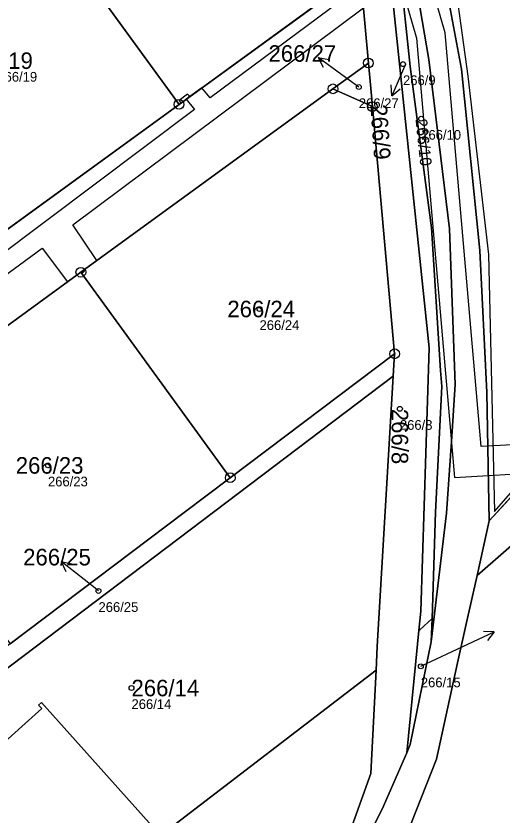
# Model space of a CAD drawing. Extents: x -734504 to -730695, y -1027923 to -1024502.
# Drawn here: x -732118.1 to -732068.2, y -1026667.3 to -1026585.2 of the extents above; entities that cross this region are included whole.
import ezdxf

# ---------------------------------------------------------------- set-up
doc = ezdxf.new("R2010")
doc.units = 0
for name, color, linetype in [('Definiční body', 7, 'Continuous'), ('Hranice parcel', 7, 'Continuous'), ('Parcelní čísla', 7, 'Continuous'), ('Polygon budovy', 7, 'Continuous'), ('Polygon parcely', 7, 'Continuous'), ('Pop  PČ popisy', 7, 'Continuous'), ('Vnitřní kresba', 7, 'Continuous'), ('Věcná břemena k části', 7, 'Continuous'), ('Značky bodu BP', 7, 'Continuous')]:
    doc.layers.add(name, color=color, linetype=linetype)

msp = doc.modelspace()

# ---------------------------------------------------------------- linework, layer by layer
at = {"layer": 'Definiční body'}
for centre in [(-732078.39, -1026590.18), (-732082.93, -1026592.54), (-732076.52, -1026595.79), (-732093.13, -1026615.33), (-732078.71, -1026625.58), (-732114.86, -1026631.39), (-732109.67, -1026644.28), (-732076.56, -1026652.02), (-732106.28, -1026654.25)]:
    msp.add_circle(centre, 0.25, dxfattribs=at)
at = {"layer": 'Hranice parcel'}
for p, q in [((-732101.4, -1026594.32), (-732117.64, -1026571.97)), ((-732085.4, -1026582.68), (-732101.4, -1026594.32)), ((-732081.95, -1026590.07), (-732085.59, -1026592.72)), ((-732081.54, -1026594.55), (-732081.95, -1026590.07)), ((-732075.48, -1026607), (-732077.67, -1026590.42)), ((-732111.48, -1026611.55), (-732085.59, -1026592.72)), ((-732085.59, -1026592.72), (-732081.54, -1026594.55)), ((-732101.4, -1026594.32), (-732123.02, -1026610.05)), ((-732081.54, -1026594.55), (-732079.25, -1026619.93)), ((-732111.48, -1026611.55), (-732134.37, -1026628.21)), ((-732096.14, -1026632.66), (-732111.48, -1026611.55)), ((-732096.14, -1026632.66), (-732079.25, -1026619.93)), ((-732079.25, -1026619.93), (-732079.39, -1026622.21)), ((-732075.07, -1026636.19), (-732074.42, -1026623.29)), ((-732069.53, -1026637.07), (-732059.39, -1026626.01)), ((-732075.41, -1026647.11), (-732075.07, -1026636.19)), ((-732070.78, -1026642.68), (-732069.53, -1026637.07)), ((-732075.41, -1026647.11), (-732075.49, -1026649.51)), ((-732081.15, -1026652.43), (-732103.29, -1026669.4))]:
    msp.add_line(p, q, dxfattribs=at)
for points in [[(-732086.41, -1026542.06), (-732080.33, -1026557.64), (-732075.27, -1026575.33), (-732072.4, -1026590.69), (-732070.5, -1026609.31), (-732069.79, -1026623.89), (-732069.53, -1026637.07)], [(-732076.75, -1026648.35), (-732076.55, -1026646.37), (-732075.69, -1026619.32), (-732079.57, -1026582.28), (-732086.17, -1026561.64), (-732086.4, -1026560.3), (-732088.47, -1026548.35)], [(-732077.67, -1026590.42), (-732078.73, -1026580.32), (-732086.16, -1026553.19)], [(-732086.16, -1026553.19), (-732083.43, -1026558.91), (-732078, -1026576.45), (-732075.75, -1026589.72), (-732073.63, -1026607.11), (-732073.03, -1026623.08), (-732073.42, -1026628.94), (-732073.91, -1026636.29), (-732075.49, -1026649.51)], [(-732081.95, -1026590.07), (-732082.69, -1026581.82), (-732082.97, -1026580.91)], [(-732074.42, -1026623.29), (-732074.53, -1026621.63), (-732075.48, -1026607)], [(-732079.39, -1026622.21), (-732119.88, -1026652.84), (-732149.94, -1026675.3)], [(-732079.39, -1026622.21), (-732081.03, -1026649.98), (-732081.15, -1026652.43)], [(-732118.74, -1026649.72), (-732100.88, -1026636.22), (-732096.14, -1026632.66)], [(-732051.94, -1026652.37), (-732063.21, -1026636.08), (-732070.78, -1026642.68)], [(-732081.19, -1026674.75), (-732078.62, -1026670.82), (-732074.95, -1026661.55), (-732072.78, -1026651.68), (-732071.93, -1026647.84), (-732070.78, -1026642.68)], [(-732076.75, -1026648.35), (-732076.65, -1026648.26), (-732075.41, -1026647.11)], [(-732078.01, -1026660.91), (-732076.89, -1026649.73), (-732076.75, -1026648.35)], [(-732075.49, -1026649.51), (-732077.64, -1026660.06), (-732078.01, -1026660.91)], [(-732081.15, -1026652.43), (-732081.68, -1026663.02), (-732085.81, -1026674.51), (-732086.55, -1026676.59), (-732088.46, -1026679.11), (-732106.83, -1026703.27), (-732115.51, -1026735.85)], [(-732103.29, -1026669.4), (-732115.52, -1026655.74), (-732115.82, -1026656.01), (-732115.48, -1026656.35), (-732129.32, -1026668.77), (-732129.68, -1026668.38), (-732129.98, -1026668.64), (-732129.76, -1026668.87), (-732133.17, -1026671.93), (-732133.06, -1026672.06), (-732144.01, -1026681.84), (-732133.82, -1026693.23)], [(-732078.01, -1026660.91), (-732080.52, -1026666.69), (-732085.45, -1026676.38), (-732094.78, -1026689.62), (-732101.27, -1026699.84), (-732104.6, -1026706.03), (-732108.31, -1026714.1), (-732110.93, -1026727.59), (-732113.44, -1026738.16)]]:
    msp.add_lwpolyline(points, dxfattribs=at)
at = {"layer": 'Polygon budovy'}
msp.add_lwpolyline([(-732129.32, -1026668.77), (-732129.68, -1026668.38), (-732129.98, -1026668.64), (-732129.76, -1026668.87), (-732133.17, -1026671.93), (-732133.06, -1026672.06), (-732144.01, -1026681.84), (-732133.82, -1026693.23), (-732131.34, -1026696.01), (-732123.7, -1026689.18), (-732125.7, -1026686.96), (-732129.61, -1026682.64), (-732122.96, -1026676.63), (-732118.56, -1026681.51), (-732116.77, -1026683.49), (-732116.46, -1026683.21), (-732116.82, -1026682.8), (-732102.94, -1026670.41), (-732102.63, -1026670.78), (-732102.31, -1026670.49), (-732103.29, -1026669.4), (-732115.52, -1026655.74), (-732115.82, -1026656.01), (-732115.48, -1026656.35)], close=True, dxfattribs=at)
at = {"layer": 'Polygon parcely'}
for points in [[(-732099.35, -1026531.16), (-732090.45, -1026544.21), (-732088.47, -1026548.35), (-732086.16, -1026553.19), (-732083.43, -1026558.91), (-732078, -1026576.45), (-732075.75, -1026589.72), (-732073.63, -1026607.11), (-732073.03, -1026623.08), (-732073.42, -1026628.94), (-732073.91, -1026636.29), (-732075.49, -1026649.51), (-732077.64, -1026660.06), (-732078.01, -1026660.91), (-732080.52, -1026666.69), (-732085.45, -1026676.38)], [(-732078.62, -1026670.82), (-732074.95, -1026661.55), (-732072.78, -1026651.68), (-732071.93, -1026647.84), (-732070.78, -1026642.68), (-732069.53, -1026637.07), (-732069.79, -1026623.89), (-732070.5, -1026609.31), (-732072.4, -1026590.69), (-732075.27, -1026575.33), (-732080.33, -1026557.64), (-732086.41, -1026542.06)], [(-732082.69, -1026581.82), (-732081.95, -1026590.07), (-732081.54, -1026594.55), (-732079.25, -1026619.93), (-732079.39, -1026622.21), (-732081.03, -1026649.98), (-732081.15, -1026652.43), (-732081.68, -1026663.02), (-732085.81, -1026674.51)], [(-732085.45, -1026676.38), (-732080.52, -1026666.69), (-732078.01, -1026660.91), (-732076.89, -1026649.73), (-732076.75, -1026648.35), (-732076.55, -1026646.37), (-732075.69, -1026619.32), (-732079.57, -1026582.28)]]:
    msp.add_lwpolyline(points, dxfattribs=at)
for points in [[(-732070.5, -1026609.31), (-732069.79, -1026623.89), (-732069.53, -1026637.07), (-732059.39, -1026626.01), (-732059.07, -1026625.66), (-732035.48, -1026606.53), (-732032.04, -1026600.26), (-732048.29, -1026578.92), (-732057.25, -1026564.44), (-732061.67, -1026537.42), (-732086.41, -1026542.06), (-732080.33, -1026557.64), (-732075.27, -1026575.33), (-732072.4, -1026590.69)], [(-732075.41, -1026647.11), (-732075.07, -1026636.19), (-732074.42, -1026623.29), (-732074.53, -1026621.63), (-732075.48, -1026607), (-732077.67, -1026590.42), (-732078.73, -1026580.32), (-732086.16, -1026553.19), (-732088.47, -1026548.35), (-732086.4, -1026560.3), (-732086.17, -1026561.64), (-732079.57, -1026582.28), (-732075.69, -1026619.32), (-732076.55, -1026646.37), (-732076.75, -1026648.35), (-732076.65, -1026648.26)], [(-732075.49, -1026649.51), (-732073.91, -1026636.29), (-732073.42, -1026628.94), (-732073.03, -1026623.08), (-732073.63, -1026607.11), (-732075.75, -1026589.72), (-732078, -1026576.45), (-732083.43, -1026558.91), (-732086.16, -1026553.19), (-732078.73, -1026580.32), (-732077.67, -1026590.42), (-732075.48, -1026607), (-732074.53, -1026621.63), (-732074.42, -1026623.29), (-732075.07, -1026636.19), (-732075.41, -1026647.11)], [(-732085.4, -1026582.68), (-732083.86, -1026578.04), (-732091.36, -1026553.86), (-732117.64, -1026571.97), (-732101.4, -1026594.32)], [(-732101.4, -1026594.32), (-732117.64, -1026571.97), (-732128.74, -1026579.61), (-732139.51, -1026587.35), (-732123.02, -1026610.05)], [(-732123.02, -1026610.05), (-732144.47, -1026625.66), (-732165.79, -1026641.17), (-732182.83, -1026653.57), (-732185.26, -1026655.34), (-732179.65, -1026661.14), (-732175.4, -1026658.05), (-732156.82, -1026644.53), (-732134.37, -1026628.21), (-732111.48, -1026611.55), (-732085.59, -1026592.72), (-732081.95, -1026590.07), (-732082.69, -1026581.82), (-732082.97, -1026580.91), (-732085.4, -1026582.68), (-732101.4, -1026594.32)], [(-732081.95, -1026590.07), (-732085.59, -1026592.72), (-732081.54, -1026594.55)], [(-732079.25, -1026619.93), (-732081.54, -1026594.55), (-732085.59, -1026592.72), (-732111.48, -1026611.55), (-732096.14, -1026632.66)], [(-732111.48, -1026611.55), (-732134.37, -1026628.21), (-732118.74, -1026649.72), (-732100.88, -1026636.22), (-732096.14, -1026632.66)], [(-732118.74, -1026649.72), (-732129.29, -1026657.7), (-732140.85, -1026666.5), (-732150.94, -1026674.18), (-732149.94, -1026675.3), (-732119.88, -1026652.84), (-732079.39, -1026622.21), (-732079.25, -1026619.93), (-732096.14, -1026632.66), (-732100.88, -1026636.22)], [(-732149.94, -1026675.3), (-732159.68, -1026682.58), (-732145.52, -1026697.86), (-732143.18, -1026700.82), (-732133.82, -1026693.23), (-732144.01, -1026681.84), (-732133.06, -1026672.06), (-732133.17, -1026671.93), (-732129.76, -1026668.87), (-732129.98, -1026668.64), (-732129.68, -1026668.38), (-732129.32, -1026668.77), (-732115.48, -1026656.35), (-732115.82, -1026656.01), (-732115.52, -1026655.74), (-732103.29, -1026669.4), (-732081.15, -1026652.43), (-732081.03, -1026649.98), (-732079.39, -1026622.21), (-732119.88, -1026652.84)], [(-732045.65, -1026652.86), (-732059.39, -1026626.01), (-732069.53, -1026637.07), (-732070.78, -1026642.68), (-732063.21, -1026636.08), (-732051.94, -1026652.37), (-732047.16, -1026654.12)], [(-732051.94, -1026652.37), (-732063.21, -1026636.08), (-732070.78, -1026642.68), (-732071.93, -1026647.84), (-732072.78, -1026651.68), (-732074.95, -1026661.55), (-732078.62, -1026670.82), (-732081.19, -1026674.75), (-732082.76, -1026680.62), (-732077.75, -1026677.66), (-732064.38, -1026665.85)], [(-732078.01, -1026660.91), (-732077.64, -1026660.06), (-732075.49, -1026649.51), (-732075.41, -1026647.11), (-732076.65, -1026648.26), (-732076.75, -1026648.35), (-732076.89, -1026649.73)], [(-732081.15, -1026652.43), (-732103.29, -1026669.4), (-732102.31, -1026670.49), (-732102.63, -1026670.78), (-732102.94, -1026670.41), (-732116.82, -1026682.8), (-732116.46, -1026683.21), (-732116.77, -1026683.49), (-732118.56, -1026681.51), (-732125.7, -1026686.96), (-732123.7, -1026689.18), (-732131.34, -1026696.01), (-732133.82, -1026693.23), (-732143.18, -1026700.82), (-732115.51, -1026735.85), (-732106.83, -1026703.27), (-732088.46, -1026679.11), (-732086.55, -1026676.59), (-732085.81, -1026674.51), (-732081.68, -1026663.02)], [(-732122.96, -1026676.63), (-732118.56, -1026681.51), (-732116.77, -1026683.49), (-732116.46, -1026683.21), (-732116.82, -1026682.8), (-732102.94, -1026670.41), (-732102.63, -1026670.78), (-732102.31, -1026670.49), (-732103.29, -1026669.4), (-732115.52, -1026655.74), (-732115.82, -1026656.01), (-732115.48, -1026656.35), (-732129.32, -1026668.77), (-732129.68, -1026668.38), (-732129.98, -1026668.64), (-732129.76, -1026668.87), (-732133.17, -1026671.93), (-732133.06, -1026672.06), (-732144.01, -1026681.84), (-732133.82, -1026693.23), (-732131.34, -1026696.01), (-732123.7, -1026689.18), (-732125.7, -1026686.96), (-732129.61, -1026682.64)]]:
    msp.add_lwpolyline(points, close=True, dxfattribs=at)
at = {"layer": 'Pop  PČ popisy'}
for p, q in [((-732084.68, -1026591.28), (-732087.108, -1026589.516)), ((-732087.108, -1026589.516), (-732086.003, -1026589.7)), ((-732087.108, -1026589.516), (-732086.592, -1026590.51)), ((-732078.35, -1026590.68), (-732079.523, -1026593.442)), ((-732078.15, -1026590.21), (-732078.35, -1026590.68)), ((-732082.93, -1026592.54), (-732084.68, -1026591.28)), ((-732079.523, -1026593.442), (-732079.592, -1026592.325)), ((-732079.523, -1026593.442), (-732078.67, -1026592.716)), ((-732111.15, -1026643.12), (-732113.515, -1026641.272)), ((-732113.515, -1026641.272), (-732112.417, -1026641.494)), ((-732113.515, -1026641.272), (-732113.034, -1026642.284)), ((-732109.67, -1026644.28), (-732111.15, -1026643.12)), ((-732071.74, -1026649.76), (-732069.02, -1026648.492)), ((-732069.02, -1026648.492), (-732070.139, -1026648.461)), ((-732069.02, -1026648.492), (-732069.716, -1026649.369)), ((-732076.56, -1026652.02), (-732071.74, -1026649.76))]:
    msp.add_line(p, q, dxfattribs=at)
at = {"layer": 'Vnitřní kresba'}
msp.add_lwpolyline([(-732061.13, -1026537.35), (-732085.01, -1026542.48), (-732078.92, -1026559.32), (-732073.63, -1026577.76), (-732071.73, -1026591.42), (-732069.62, -1026609.74), (-732068.98, -1026636.13), (-732059.46, -1026625.23), (-732039.49, -1026615.52), (-732026.13, -1026613.13), (-732013.67, -1026616.52), (-731996.27, -1026634.52), (-731967.83, -1026652.33), (-731949.59, -1026613.99), (-731927.58, -1026565.74), (-731904.67, -1026526.33)], dxfattribs=at)
at = {"layer": 'Věcná břemena k části'}
for points in [[(-732099.35, -1026531.16), (-732090.45, -1026544.21), (-732088.47, -1026548.35), (-732086.94, -1026553.18), (-732077.02, -1026587.52), (-732073.1, -1026632.62), (-732069.62, -1026632.42), (-732065.03, -1026632.16), (-732056.49, -1026631.67), (-732032.51, -1026630.31), (-732025.2, -1026631.69), (-732022.86, -1026629.07), (-732032.31, -1026627.29), (-732057.99, -1026628.75), (-732062.12, -1026628.99), (-732069.68, -1026629.42), (-732070.36, -1026629.46), (-732074.06, -1026586.96), (-732084.18, -1026551.92), (-732101.02, -1026526)], [(-732082.67, -1026582.07), (-732098.21, -1026593.63), (-732099.04, -1026592.61), (-732100.66, -1026593.78), (-732099.82, -1026594.83), (-732120.39, -1026610.28)], [(-732157.49, -1026639.94), (-732115.46, -1026609.08), (-732112.85, -1026612.55), (-732111.48, -1026611.55), (-732109.84, -1026610.36), (-732112.29, -1026606.7), (-732082.46, -1026584.41)]]:
    msp.add_lwpolyline(points, dxfattribs=at)
for points in [[(-732101.21, -1026594.18), (-732100.41, -1026593.6), (-732100.36, -1026593.45), (-732100.52, -1026593.27), (-732101.39, -1026593.91)], [(-732111.48, -1026611.55), (-732111.4, -1026611.66), (-732111.11, -1026611.43), (-732111.19, -1026611.34)]]:
    msp.add_lwpolyline(points, close=True, dxfattribs=at)
at = {"layer": 'Značky bodu BP'}
for centre, radius in [((-732081.95, -1026590.07), 0.5), ((-732081.95, -1026590.07), 0.0303), ((-732085.59, -1026592.72), 0.5), ((-732085.59, -1026592.72), 0.0303), ((-732101.4, -1026594.32), 0.5), ((-732101.4, -1026594.32), 0.0303), ((-732081.54, -1026594.55), 0.5), ((-732081.54, -1026594.55), 0.0303), ((-732111.48, -1026611.55), 0.5), ((-732111.48, -1026611.55), 0.0303), ((-732079.25, -1026619.93), 0.5), ((-732079.25, -1026619.93), 0.0303), ((-732096.14, -1026632.66), 0.5), ((-732096.14, -1026632.66), 0.0303)]:
    msp.add_circle(centre, radius, dxfattribs=at)

# ---------------------------------------------------------------- texts
at = {"layer": 'Definiční body'}
for s, p in [('266/19', (-732120.06, -1026591.986)), ('266/9', (-732078.39, -1026592.336)), ('266/27', (-732082.93, -1026594.696)), ('266/10', (-732076.52, -1026597.946)), ('266/24', (-732093.13, -1026617.486)), ('266/8', (-732078.71, -1026627.736)), ('266/23', (-732114.86, -1026633.546)), ('266/25', (-732109.67, -1026646.436)), ('266/15', (-732076.56, -1026654.176)), ('266/14', (-732106.28, -1026656.406))]:
    msp.add_text(s, height=1, dxfattribs=at).set_placement(p)
at = {"layer": 'Parcelní čísla'}
for s, p in [('266/27', (-732092.205, -1026589.94)), ('266/19', (-732123.365, -1026590.679)), ('266/24', (-732096.435, -1026616.179)), ('266/23', (-732118.165, -1026632.24)), ('266/25', (-732117.405, -1026641.66)), ('266/14', (-732106.28, -1026655.1))]:
    msp.add_text(s, height=1.7, dxfattribs=at).set_placement(p)
for s, height, rotation, p in [('266/9', 1.7, 274, (-732081.743, -1026594.374)), ('266/10', 1.19, 276, (-732077.111, -1026595.852)), ('266/8', 1.7, 270, (-732079.559, -1026625.58))]:
    msp.add_text(s, height=height, rotation=rotation, dxfattribs=at).set_placement(p)

doc.saveas('drawing.dxf')
